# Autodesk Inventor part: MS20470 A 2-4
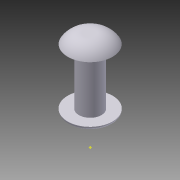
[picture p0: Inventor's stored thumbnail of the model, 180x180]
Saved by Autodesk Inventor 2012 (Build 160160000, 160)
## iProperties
Created: 2004-10
Part Number: MS20470 A 2-4
Document SubType Name: Modeling
Designer: Autodesk, Inc.
Manufacturer: Standard
Standards Organization: Custom
Material: Aluminum-6061
Description: #2 x 0.25 RIVET, SOLID, UNIVERSAL HEAD
Mass: 0.0360393 g
Surface Area: 0.509577 cm^2
Volume: 0.0132986 cm^3
Density: 2.71 g/cm^3
CAGE: 1LJX3
Dept. ID: Product Design
Description #2: ---
Finish #1: ---
Finish #2: ---
Material ID: ---
Project Number: ---
Author: Autodesk, Inc.
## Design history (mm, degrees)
sketch "Sketch1"
  geometry: C1 r 0.8 at (0, 0)
  constraints: 1 centre point
  dimensions: "d0" = 1.6002 diameter of C1 (= Dim_D)
extrude "Body" new body sketch "Sketch1" distance "d1" = 3.9624 (= Engage_Length); taper "d2" = 0 deg
sketch "Sketch2"
  geometry: L1 (-0.328, 0)-(1.968, 0) reference; L2 (0, -6.828)-(0, -3.485) reference; L3 (0, -3.962)-(1.587, -3.962); L4 (1.587, -3.962)-(1.587, -3.962); L5 (1.333, -4.216)-(0, -4.216); L6 (0, -4.216)-(0, -3.962); A1 r 0.254 centre (1.333, -3.962) between (1.333, -4.216) and (1.587, -3.962); 2 further points
  constraints: 8 end point, 4 point on line, 2 parallel, 2 point on circle, 2 tangent, 1 centre point, 1 horizontal, 1 perpendicular
  dimensions: "d3" = 3.9624 distance between parallel lines of L3 L1 (= Engage_Length); "d4" = 3.175 diameter of L4 L2 (= Dim_A); "d5" = 0.254 distance of L3.end point (1.587, -4.216) (= 0.5 x Dim_T); "d6" = 0.254 radius of A1 (= d5); "d11" = 6.35 distance from line of point (0, -6.35) L1 (= Length)
revolve "Deformation" stored, may be unused: angle "d7" = 90 deg
node "Undeformed Length"
sketch "Sketch4"
  geometry: L1 (-0.317, 0)-(1.905, 0) reference; L2 (0, -4.755)-(0, 0.792) reference; L3 (0, 0)-(1.587, 0); L4 (1.587, 0)-(1.587, -0.102); L5 (1.587, -0.102)-(0.8, -0.762); L6 (0.8, -0.762)-(0, -0.762); L7 (0.8, 0)-(0.8, -3.962) reference
  constraints: 8 end point, 5 point on line, 2 perpendicular
  dimensions: "d12" = 3.175 diameter of L4 L2 (= Dim_A); "d13" = 0.1016 distance of L3.end L4.end (= Dim_E_CSink); "d14" = 50 deg angle of L2 L5; "d22" = 0.66071 distance from line of L6 L4.end (derived)
revolve "CSink Head" sketch "Sketch4" stored, may be unused: angle "d15" = 90 deg
sketch "Sketch5"
  geometry: L1 (0, -0.992)-(0, 1.151) reference; L2 (-0.335, 0)-(2.008, 0) reference; L3 (0, 0.686)-(0.394, 0.686); L4 (1.582, 0)-(0, 0); A1 r 1.372 centre (0.394, -0.686) between (1.582, 0) and (0.394, 0.686)
  constraints: 4 end point, 4 point on line, 2 point on circle, 1 centre point, 1 parallel, 1 tangent
  dimensions: "d16" = 0.7874 diameter of L3.end L1 (= Dim_E_Univ); "d17" = 1.3716 radius of A1 (= Dim_R); "d18" = 0.3937 distance from line of A1.centre L1 (derived); "d19" = 0.6858 distance between parallel lines of L3 L2 (= Dim_C)
revolve "Universal Head" sketch "Sketch5" stored, may be unused: angle "d20" = 90 deg
body "Solid1"
other parameters: "Dim_A" = 3.175 [user parameter; used in 2 equation terms], "Dim_B" = 2.3876 [user parameter; used in 1 equation term], "Dim_C_CSink" = 2.3876 (= Dim_B) [user parameter; used in 1 equation term], "Dim_D" = 1.6002 [user parameter; used in 1 equation term], "Dim_E_CSink" = 0.1016 [user parameter; used in 1 equation term], "Dim_S" = 0.5842 [user parameter], "Dim_T" = 0.508 [user parameter; used in 1 equation term], "Engage_Length" = 3.9624 (= Length - Dim_C_CSink) [user parameter; used in 2 equation terms], "Length" = 6.35 [user parameter; used in 2 equation terms], "Dim_E_Univ" = 0.7874 [user parameter; used in 1 equation term], "Dim_F" = 0.5842 [user parameter], "Dim_R" = 1.3716 [user parameter; used in 1 equation term], "Dim_C" = 0.6858 [user parameter; used in 1 equation term]
